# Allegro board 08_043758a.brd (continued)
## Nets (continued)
DDR3_A10: R21.1(N1) U2.L7(A10/AP) U4.J1(PS_DDR_A10_502)
DDR3_A11: R27.1(N1) U2.R7(A11) U4.L2(PS_DDR_A11_502)
DDR3_A12: R28.1(N1) U2.N7(A12/BC#) U4.M2(PS_DDR_A12_502)
DDR3_A13: R34.1(N1) U2.T3(A13) U4.K2(PS_DDR_A13_502)
DDR3_A14: R29.1(N1) U2.T7(A14) U4.K1(PS_DDR_A14_502)
DDR3_BA0: R35.1(N1) U2.M2(BA0) U4.M6(PS_DDR_BA0_502)
DDR3_BA1: R30.1(N1) U2.N8(BA1) U4.R1(PS_DDR_BA1_502)
DDR3_BA2: R36.1(N1) U2.M3(BA2) U4.N6(PS_DDR_BA2_502)
DDR3_CAS#: R32.1(N1) U2.K3(CAS#) U4.R5(PS_DDR_CAS_B_502)
DDR3_CK_N: R142.2(N2) U2.K7(CK#) U4.N2(PS_DDR_CKN_502)
DDR3_CK_P: R142.1(N1) U2.J7(CK) U4.N3(PS_DDR_CKP_502)
DDR3_CKE: R38.1(N1) U2.K9(CKE) U4.L3(PS_DDR_CKE_502)
DDR3_CS#: R39.1(N1) U2.L2(CS#) U4.R2(PS_DDR_CS_B_502)
DDR3_DM0: U2.E7(LDM) U4.B1(PS_DDR_DM0_502)
DDR3_DM1: U2.D3(UDM) U4.D3(PS_DDR_DM1_502)
DDR3_DQ0: U2.E3(DQ0) U4.D4(PS_DDR_DQ0_502)
DDR3_DQ1: U2.F7(DQ1) U4.A2(PS_DDR_DQ1_502)
DDR3_DQ2: U2.F2(DQ2) U4.C4(PS_DDR_DQ2_502)
DDR3_DQ3: U2.F8(DQ3) U4.C1(PS_DDR_DQ3_502)
DDR3_DQ4: U2.H3(DQ4) U4.B4(PS_DDR_DQ4_502)
DDR3_DQ5: U2.H8(DQ5) U4.A4(PS_DDR_DQ5_502)
DDR3_DQ6: U2.G2(DQ6) U4.C3(PS_DDR_DQ6_502)
DDR3_DQ7: U2.H7(DQ7) U4.A3(PS_DDR_DQ7_502)
DDR3_DQ8: U2.D7(DQ8) U4.E1(PS_DDR_DQ8_502)
DDR3_DQ9: U2.C3(DQ9) U4.D1(PS_DDR_DQ9_502)
DDR3_DQ10: U2.C8(DQ10) U4.E2(PS_DDR_DQ10_502)
DDR3_DQ11: U2.C2(DQ11) U4.E3(PS_DDR_DQ11_502)
DDR3_DQ12: U2.A7(DQ12) U4.F3(PS_DDR_DQ12_502)
DDR3_DQ13: U2.A2(DQ13) U4.G1(PS_DDR_DQ13_502)
DDR3_DQ14: U2.B8(DQ14) U4.H1(PS_DDR_DQ14_502)
DDR3_DQ15: U2.A3(DQ15) U4.H2(PS_DDR_DQ15_502)
DDR3_DQS0_N: U2.G3(LDQS#) U4.B2(PS_DDR_DQS_N0_502)
DDR3_DQS0_P: U2.F3(LDQS) U4.C2(PS_DDR_DQS_P0_502)
DDR3_DQS1_N: U2.B7(UDQS#) U4.F2(PS_DDR_DQS_N1_502)
DDR3_DQS1_P: U2.C7(UDQS) U4.G2(PS_DDR_DQS_P1_502)
DDR3_ODT: R33.1(N1) U2.K1(ODT) U4.K3(PS_DDR_ODT_502)
DDR3_RAS#: R37.1(N1) U2.J3(RAS#) U4.R6(PS_DDR_RAS_B_502)
DDR3_RST#: R42.1(N1) U2.T2(RESET#) U4.L4(PS_DDR_DRST_B_502)
DDR3_WE#: R31.1(N1) U2.L3(WE#) U4.R3(PS_DDR_WE_B_502)
FB0: R2.2(N2) R4.1(N1) U3.4(FB)
FB_1P8V: R64.1(N1) R65.2(N2) U6.32(FB1)
FB_1P35V: R62.2(N2) R63.1(N1) U6.9(FB2)
IO_02_34_AD9361_CLKOUT: U4.P8(IO_L23P_T3_34) U5.J6(CLK_OUT)
IO_02_34_AD9361_RST: U4.P9(IO_L23N_T3_34) U5.K5(RESETB)
IO_L01_34_FB_CLK: U4.P10(IO_L24P_T3_34) U5.F10(FB_CLK_P)
IO_L01_34_RX_D0: U4.H14(IO_L3N_T0_DQS_34) U5.K11(P1_D0/RX_D0_N)
IO_L01_34_RX_D1: U4.J13(IO_L5P_T0_34) U5.J12(P1_D1/RX_D0_P)
IO_L02_34_RX_D2: U4.G14(IO_L3P_T0_DQS_PUDC_B_34) U5.K10(P1_D2/RX_D1_N)
IO_L02_34_RX_D3: U4.H13(IO_L2N_T0_34) U5.J11(P1_D3/RX_D1_P)
IO_L03_34_RX_D4: U4.G12(IO_L2P_T0_34) U5.K9(P1_D4/RX_D2_N)
IO_L03_34_RX_D5: U4.H12(IO_L1N_T0_34) U5.J10(P1_D5/RX_D2_P)
IO_L04_34_RX_D6: U4.G11(IO_L1P_T0_34) U5.K8(P1_D6/RX_D3_N)
IO_L04_34_RX_D7: U4.J14(IO_L5N_T0_34) U5.J9(P1_D7/RX_D3_P)
IO_L05_34_RX_D8: U4.J15(IO_L4P_T0_34) U5.K7(P1_D8/RX_D4_N)
IO_L05_34_RX_D9: U4.K15(IO_L4N_T0_34) U5.J8(P1_D9/RX_D4_P)
IO_L06_34_RX_D10: U4.H11(IO_L6P_T0_34) U5.J7(P1_D10/RX_D5_N)
IO_L06_34_RX_D11: U4.J11(IO_L6N_T0_VREF_34) U5.H8(P1_D11/RX_D5_P)
IO_L07_34_RX_FRAME: U4.N13(IO_L7P_T1_34) U5.G8(RX_FRAME_P)
IO_L08_34_CTRL_OUT0: U4.L15(IO_L8P_T1_34) U5.D4(CTRL_OUT0)
IO_L08_34_CTRL_OUT1: U4.M15(IO_L8N_T1_34) U5.E4(CTRL_OUT1)
IO_L09_34_TX_FRAME: U4.L14(IO_L9P_T1_DQS_34) U5.G9(TX_FRAME_P)
IO_L10_34_EN_AGC: U4.L13(IO_L10N_T1_34) U5.G5(EN_AGC)
IO_L11_34_ENABLE: U4.K12(IO_L11N_T1_SRCC_34) U5.G6(ENABLE)
IO_L11_34_TXNRX: U4.K11(IO_L11P_T1_SRCC_34) U5.H4(TXNRX)
IO_L12_MRCC_34_DATA_CLK: U4.L12(IO_L12P_T1_MRCC_34) U5.G11(DATA_CLK_P)
IO_L13_34_CTRL_OUT2: U4.N11(IO_L13P_T2_MRCC_34) U5.E5(CTRL_OUT2)
IO_L13_34_CTRL_OUT3: U4.N12(IO_L13N_T2_MRCC_34) U5.E6(CTRL_OUT3)
IO_L15_34_TX_D0: U4.P15(IO_L15P_T2_DQS_34) U5.E12(P0_D0/TX_D0_N)
IO_L15_34_TX_D1: U4.R13(IO_L17N_T2_34) U5.D11(P0_D1/RX_D0_P)
IO_L16_34_TX_D2: U4.R15(IO_L15N_T2_DQS_34) U5.E11(P0_D2/TX_D1_N)
IO_L16_34_TX_D3: U4.P11(IO_L16P_T2_34) U5.D10(P0_D3/TX_D1_P)
IO_L17_34_TX_D4: U4.R11(IO_L16N_T2_34) U5.E10(P0_D4/TX_D2_N)
IO_L17_34_TX_D5: U4.R12(IO_L17P_T2_34) U5.D9(P0_D5/TX_D2_P)
IO_L18_34_TX_D6: U4.P14(IO_L18N_T2_34) U5.E9(P0_D6/TX_D3_N)
IO_L18_34_TX_D7: U4.P13(IO_L18P_T2_34) U5.D8(P0_D7/TX_D3_P)
IO_L19_34_TX_D8: U4.N9(IO_L19N_T3_VREF_34) U5.E8(P0_D8/TX_D4_N)
IO_L19_34_TX_D9: U4.M9(IO_L19P_T3_34) U5.D7(P0_D9/TX_D4_P)
IO_L20_34_TX_D10: U4.R8(IO_L20N_T3_34) U5.F8(P0_D10/TX_D5_N)
IO_L20_34_TX_D11: U4.R7(IO_L20P_T3_34) U5.E7(P0_D11/TX_D5_P)
IO_L21_34_CTRL_OUT4: U4.M10(IO_L21P_T3_DQS_34) U5.F6(CTRL_OUT4)
IO_L21_34_CTRL_OUT5: U4.M11(IO_L21N_T3_DQS_34) U5.F5(CTRL_OUT5)
IO_L22_34_CTRL_OUT6: U4.N7(IO_L22P_T3_34) U5.F4(CTRL_OUT6)
IO_L22_34_CTRL_OUT7: U4.N8(IO_L22N_T3_34) U5.G4(CTRL_OUT7)
IO_L23_35_SPI_CLK: U4.E11(IO_L2P_T0_AD8P_35) U5.J5(SPI_CLK)
IO_L23_35_SPI_ENB: U4.E12(IO_L2N_T0_AD8N_35) U5.K6(SPI_ENB)
IO_L24_35_SPI_DI: U4.E13(IO_L1N_T0_AD0N_35) U5.J4(SPI_DI)
IO_L24_35_SPI_DO: U4.F12(IO_L1P_T0_AD0P_35) U5.L6(SPI_DO)
JTAG_TCK: P1.4(N2) U4.G9(TCK_0)
JTAG_TDI: P1.8(N4) U4.L7(TDI_0)
JTAG_TDO: P1.6(N3) U4.L8(TDO_0)
JTAG_TMS: P1.2(N1) U4.L9(TMS_0)
PG_1P0V: R6.2(N2) U3.16(PGOOD) U6.28(EN1)
PG_1P8V: R59.1(N1) U6.13(EN2) U6.29(PGOOD1)
PS-SRST#: R11.2(N2) R74.2(N2) U4.B11(PS_SRST_B_501)
PS_MIO01_500_QSPI0_SS_B: R14.2(N2) U4.A5(PS_MIO1_500) U13.C2(S#)
PS_MIO02_500_QSPI0_IO0: R120.1(N1) U4.A8(PS_MIO2_500) U13.D3(DQ0)
PS_MIO03_500_QSPI0_IO1: R119.1(N1) U4.A7(PS_MIO3_500) U13.D2(DQ1)
PS_MIO04_500_QSPI0_IO2: R121.1(N1) U4.C8(PS_MIO4_500) U13.C4(W#/VPP/DQ2)
PS_MIO05_500_QSPI0_IO3: P1.5(N3) R122.1(N1) U4.A9(PS_MIO5_500) U13.D4(HOLD#/DQ3)
PS_MIO06_500_QSPI0_SCLK: R116.1(N1) U4.A10(PS_MIO6_500) U13.B2(C)
PS_MIO07_500_USB_RESET_B: R76.2(N2) U4.A12(PS_MIO52_501) U15.27(RESETB)
PS_MIO28_501_USB0_D4: U4.A15(PS_MIO28_501) U15.7(DATA4)
PS_MIO29_501_USB0_DIR: U4.D11(PS_MIO29_501) U15.31(DIR)
PS_MIO30_501_USB0_STP: U4.B15(PS_MIO30_501) U15.29(STP)
PS_MIO31_501_USB0_NXT: U4.C12(PS_MIO31_501) U15.2(NXT)
PS_MIO32_501_USB0_D0: U4.E15(PS_MIO32_501) U15.3(DATA0)
PS_MIO33_501_USB0_D1: U4.C11(PS_MIO33_501) U15.4(DATA1)
PS_MIO34_501_USB0_D2: U4.D15(PS_MIO34_501) U15.5(DATA2)
PS_MIO35_501_USB0_D3: U4.A14(PS_MIO35_501) U15.6(DATA3)
PS_MIO36_501_USB0_CLK: U4.B14(PS_MIO36_501) U15.1(CLKOUT)
PS_MIO37_501_USB0_D5: U4.C14(PS_MIO37_501) U15.9(DATA5)
PS_MIO38_501_USB0_D6: U4.A13(PS_MIO38_501) U15.10(DATA6)
PS_MIO39_501_USB0_D7: U4.D14(PS_MIO39_501) U15.13(DATA7)
PWR_GD: R5.2(N2) U1.5(PG) U7.5(PG)
PWR_GD_1.35V: C47.1(N1) R13.2(N2) R15.1(N1) U4.C9(PS_POR_B_500) U6.12(PGOOD2)
REF_CLK_SG: R10.1(N1) R50.1(N1)
RX1A_N: C133.2(N2) U5.M2(RX1A_N)
RX1A_P: C134.2(N2) U5.M1(RX1A_P)
SCL: R79.2(N2) R86.2(N2) U4.M14(IO_L9N_T1_DQS_34) U11.2(SCLA)
SDA: R78.2(N2) R85.2(N2) U4.N14(IO_L7N_T1_34) U11.3(SDAA)
SYNC: L4.1(N1) U3.9(SW_1) U3.10(SW_2) U3.11(SW_3)
TX1A_N: C131.1(N1) L8.2(N2) U5.M8(TX1A_N)
TX1A_P: C132.1(N1) L9.2(N2) U5.M7(TX1A_P)
TX_VCO_1P1V_SUPPLY: C128.1(N1) R52.1(N1) U5.A11(VDDA1P1_TX_VCO) U5.B11(TX_VCO_LDO_OUT)
UART_RX: P1.1(N1) U4.C6(PS_MIO13_500)
UART_TX: P1.3(N2) U4.B7(PS_MIO12_500)
UNNAMED_2_ADP1754_I93_SS: C2.1(N1) U1.7(SS)
UNNAMED_2_ADP1754_I233_SS: C12.1(N1) U7.7(SS)
UNNAMED_2_ADP2164_I29_EN: C13.1(N1) R1.1(N1) U3.1(SYNC) U3.3(TRK) U3.14(VIN) U3.15(EN)
UNNAMED_2_ADP2164_I29_PVIN1: C11.1(N1) L1.2(N2) R1.2(N2) R6.1(N1) U3.12(PVIN_1) U3.13(PVIN_2)
UNNAMED_2_ADP2164_I29_RT: R3.2(N2) U3.2(RT)
UNNAMED_2_RES_I251_N2: R4.2(N2) R7.1(N1)
UNNAMED_3_ICN25Q256AV2_I26_RESE: R11.1(N1) U13.A4(RESET/NC)
UNNAMED_3_ICXC7Z010_I16_PSCLK50: R10.2(N2) R12.2(N2) U4.C7(PS_CLK_500)
UNNAMED_3_ICXC7Z010_I16_PSMIO75: R83.2(N2) U4.D9(PS_MIO7_500)
UNNAMED_3_ICXC7Z010_I16_PSMIO85: R84.1(N1) U4.B6(PS_MIO8_500)
UNNAMED_3_RES_I2_N1: R8.2(N2) R9.1(N1) Y2.1(STANDBY)
UNNAMED_3_RES_I48_N1: R12.1(N1) Y2.3(OUTPUT)
UNNAMED_4_ICMT41K256M16_I98_ZQ: R165.1(N1) U2.L8(ZQ)
UNNAMED_4_ICTPS51206_I44_S3: R222.2(N2) U14.7(S3)
UNNAMED_4_ICTPS51206_I44_S5: R221.2(N2) U14.9(S5)
UNNAMED_4_ICTPS51206_I44_VLDOIN: R44.2(N2) U14.2(VLDOIN)
UNNAMED_4_ICTPS51206_I44_VTTSNS: C80.1(N1) R43.2(N2) U14.5(VTTSNS)
UNNAMED_4_ICXC7Z010_I26_PSDDR_1: R40.1(N1) U4.H3(PS_DDR_VRP_502)
UNNAMED_4_ICXC7Z010_I26_PSDDRVR: R41.1(N1) U4.J3(PS_DDR_VRN_502)
UNNAMED_5_CAP_I17_N1: C93.1(N1) C98.1(N1) E5.2(N2) U4.F7(VCCADC_0)
UNNAMED_5_CAP_I17_N2: C93.2(N2) C98.2(N2) E6.2(N2) U4.F6(CFGBVS_0) U4.F8(GNDADC_0) U4.G8(VREFN_0) U4.H7(VREFP_0) U4.J7(DXP_0)
UNNAMED_5_DIOLED_I60_N: DS1.C(N) R48.1(N1)
UNNAMED_5_DIOLED_I62_N: DS2.C(N) R87.1(N1)
UNNAMED_5_ICXC7Z010_I13_DONE0: Q1.1(G) U4.M7(DONE_0)
UNNAMED_5_ICXC7Z010_I13_INITB0: R47.1(N1) U4.D5(INIT_B_0)
UNNAMED_5_ICXC7Z010_I13_PROGRAM: R46.1(N1) U4.K6(PROGRAM_B_0)
UNNAMED_5_ICXC7Z010_I13_VCCBATT: R45.2(N2) U4.E6(VCCBATT_0)
UNNAMED_5_RES_I61_N2: Q1.3(D) R48.2(N2)
UNNAMED_5_RES_I63_N2: Q4.3(D) R87.2(N2)
UNNAMED_7_AD9363_I13_RBIAS: R49.2(N2) U5.L4(RBIAS)
UNNAMED_7_AD9363_I13_XTALN: C123.2(N2) C124.1(N1) U5.M12(XTALN)
UNNAMED_7_CAP_I22_N2: C126.2(N2) R51.1(N1)
UNNAMED_7_CAP_I30_N1: C127.1(N1) R52.2(N2)
UNNAMED_7_CAP_I39_N2: C132.2(N2) T5.4(SEC)
UNNAMED_7_CAP_I40_N2: C131.2(N2) T5.6(SEC_DOT)
UNNAMED_7_CAP_I51_N1: C134.1(N1) T1.4(SEC)
UNNAMED_7_CAP_I52_N1: C133.1(N1) T1.6(SEC_DOT)
UNNAMED_7_CAP_I53_N1: C123.1(N1) R50.2(N2) Y3.3(OUT)
UNNAMED_7_CNBNC5P_I55_CNTR: RX1A.1(CNTR) T1.3(PRI_DOT)
UNNAMED_7_CNBNC5P_I56_CNTR: T5.3(PRI_DOT) TX1A.1(CNTR)
UNNAMED_9_ADM1177_I23_GATE: Q3.1(G) U10.10(GATE)
UNNAMED_9_ADM1177_I23_ON: R71.2(N2) R72.1(N1) U10.3(ON)
UNNAMED_9_ADM1177_I23_SENSE: Q3.3(D) R73.2(N2) U10.2(SENSE)
UNNAMED_9_ADM1177_I23_SS: C155.1(N1) U10.9(SS)
UNNAMED_9_ADM1177_I23_TIMER: C156.1(N1) U10.5(TIMER)
UNNAMED_9_ADP2114_I196_FREQ: R53.2(N2) U6.3(FREQ)
UNNAMED_9_ADP2114_I196_OPCFG: R54.1(N1) U6.6(OPCFG)
UNNAMED_9_ADP2114_I196_SS1: C7.2(N2) U6.30(SS1)
UNNAMED_9_ADP2114_I196_SS2: C139.2(N2) U6.11(SS2)
UNNAMED_9_ADP2114_I196_SW1: L3.1(N1) U6.23(SW2) U6.24(SW1)
UNNAMED_9_ADP2114_I196_SW3: L2.1(N1) U6.17(SW4) U6.18(SW3)
UNNAMED_9_CAP_I163_N1: C146.1(N1) L3.2(N2) L5.1(N1)
UNNAMED_9_CAP_I214_N2: C147.2(N2) R60.2(N2)
UNNAMED_9_CAP_I224_N2: C144.2(N2) R61.2(N2)
UNNAMED_9_CAP_I306_N1: C149.1(N1) C150.1(N1) E3.1(N1) L5.2(N2) R64.2(N2)
UNNAMED_9_CN5P3SHLD_I255_N6: P2.SH1(N6) P2.SH2(N7) P2.SH3(N8) R55.1(N1)
UNNAMED_9_CN5P3SHLD_I256_N6: P3.SH1(N6) P3.SH2(N7) P3.SH3(N8) R58.1(N1)
UNNAMED_9_FERRITE_I303_N1: E7.1(N1) Q3.2(S)
UNNAMED_9_ICNCP339_I277_EN: R68.2(N2) R69.1(N1) U8.C2(EN)
UNNAMED_9_ICNCP339_I278_EN: Q2.3(D) R70.2(N2) U9.C2(EN)
UNNAMED_9_RES_I270_N1: Q2.1(G) R66.2(N2) R67.1(N1)
UNNAMED_11_ICUSB3320C_I29_RBIAS: R77.1(N1) U15.24(RBIAS)
UNNAMED_11_ICUSB3320C_I29_REFCL: R82.1(N1) U15.26(REFCLK)
UNNAMED_11_ICUSB3320C_I29_VBUS: R75.2(N2) U15.22(VBUS)
UNNAMED_11_ICXC7Z010_I11_PSMI_1: R85.1(N1) U4.D13(PS_MIO49_501)
UNNAMED_11_ICXC7Z010_I11_PSMIO4: R86.1(N1) U4.B12(PS_MIO48_501)
UNNAMED_11_RES_I67_N2: R82.2(N2) Y1.3(OUTPUT)
USB_OTG_N: D2.C(N) P2.2(N2) U15.19(DM)
USB_OTG_P: D1.C(N) P2.3(N3) U15.18(DP)
USR_LED: Q4.1(G) U4.K13(IO_L10P_T1_34)
VTT_0P75: C79.1(N1) C101.1(N1) R16.2(N2) R17.2(N2) R18.2(N2) R19.2(N2) R20.2(N2) R21.2(N2) R22.2(N2) R23.2(N2) R24.2(N2) R25.2(N2) R26.2(N2) R27.2(N2) R28.2(N2) R29.2(N2) R30.2(N2) R31.2(N2) R32.2(N2) R33.2(N2) R34.2(N2) R35.2(N2) R36.2(N2) R37.2(N2) R38.2(N2) R39.2(N2) R43.1(N1) U14.3(VTT)
VTTVREF: C63.2(N2) C81.1(N1) C84.1(N1) C99.2(N2) C102.1(N1) U2.H1(VREFDQ) U2.M8(VREFCA) U4.F4(PS_DDR_VREF0_502) U14.6(VTTREF)

Pads without a net: P2 4; P3 2 3 4; U1 8; U2 J1 J9 L1 L9 M7; U4 B5 B9 B10 C13 D6 D8 D10 G7 H8 M12 R10; U5 A3 B3 B4 B5 B6 B7 C3 G7 H11 L5 M3 M11; U6 5; U7 8; U10 8; U11 5; U13 A2 A3 A5 B1 B5 C1 C3 C5 D1 D5 E1 E2 E3 E4 E5; U15 12 15 16 17 25; Y1 1; Y3 1

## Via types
v1: diameter 0.508, hole 0.254, TOP to BOTTOM, 797 vias
v2: diameter 0.406, hole 0.203, TOP to BOTTOM, 583 vias

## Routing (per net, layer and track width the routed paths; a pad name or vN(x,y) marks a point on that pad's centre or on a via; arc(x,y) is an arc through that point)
1.0V: length 20.7
  TOP w0.762: E1.1 74.65,15.95 ; E1.1 73.82,16.84 ; E1.1 73.82,15.06 ; 85.13,14.81 L4.2 ; L4.2 86.12,12.71 ; L4.2 86.12,16.9 ; 80.07,16.77 C17.1 ; C17.1 81.13,15.87 ; C17.1 82.18,16.77 ; 82.48,16.77 C21.1 ; C21.1 84.59,16.77 ; C21.1 83.54,15.87 ; C20.1 79.77,16.77 ; C20.1 77.66,16.77 ; C20.1 78.71,15.87 ; 76.3,15.87 C19.1 ; C19.1 77.35,16.77 ; C19.1 75.25,16.77
  BOTTOM w0.305: R7.2 v1(84.94,17.1)
1.35V: length 16.2
  TOP w0.762: C145.1 82.56,55.76 ; C145.1 81.51,56.67 ; C145.1 80.45,55.76 ; L2.2 88.11,56.53 ; L2.2 90.21,55.53 ; L2.2 86.01,55.53 ; C148.1 85.1,55.76 ; C148.1 82.99,55.76 ; C148.1 84.05,56.67 ; 79.28,56.72 E2.1 80.11,55.83
  BOTTOM w0.305: R62.1 92.3,55.99 92.3,56.59 92.05,56.84 v1(90.27,56.84)
1V8: length 123.4
  TOP w0.203: U1.4 20.63,9.26 20.47,9.09 20.1,9.09 19.98,9.21 ; 41.57,9.21 41.69,9.09 42.06,9.09 42.22,9.26 U7.4
  TOP w0.305: v1(75.79,29.28) 75.8,29.27 U15.30 ; U4.G4 v2(55.53,36.95) ; U11.1 57.61,14.26 C166.2 57.06,15.25 v1(57.24,15.43) ; U15.32 74.8,28.62 v1(74.27,29.16) ; U4.A6 v2(60.43,34.95) ; v1(82.27,30.68) C163.2 80.93,31.25 Y1.4 ; U4.K8 v2(52.33,33.75) ; U4.H4 v2(54.73,36.95) ; C10.1 41.57,8.91 ; C10.1 41.57,8 ; C10.1 41.16,8.46 ; Y3.4 25.06,17.67 C122.1 25.06,14.58 C121.1 25.37,14.21 v1(25.37,13.28) ; 18.25,9.98 U1.1 ; U1.1 18.68,9.21 ; U1.1 U1.2 U1.3 19.98,9.21 ; U4.N10 v2(49.93,31.35) ; 16.98,10.91 U1.16 ; U1.16 17.76,10.48 ; U1.16 U1.15 ; U4.E14 v2(57.13,28.15) ; v1(55.47,12.01) R78.1 ; R47.2 v1(65.12,39.32) ; U4.L6 v2(52.33,34.55) ; R84.2 v1(67.66,38.54) ; U15.8 v1(74.1,23.44) ; U15.14 77.3,22.44 v1(77.44,22.3) ; U4.R14 v2(48.33,28.15) ; C25.1 31.94,12.27 ; C25.1 31.53,12.72 ; C25.1 31.53,11.81 ; U4.C10 v2(58.73,31.35) ; U4.P7 v2(49.13,34.55) ; 38.57,10.91 U7.16 ; U7.16 U7.15 ; U7.16 39.35,10.48 ; 40.27,9.21 U7.1 ; U7.1 39.84,9.98 ; U7.1 U7.2 U7.3 41.57,9.21 ; U4.H9 v2(54.73,32.95) ; U4.D7 v2(57.93,34.55) ; 19.57,8.46 C1.1 ; C1.1 19.98,8.91 ; C1.1 19.98,8 ; U4.M13 v2(50.73,28.95) ; U13.B4 v2(73.61,45.31) ; U4.F11 v2(56.33,30.55) ; U4.J4 v2(53.13,36.95) ; U4.J6 v2(53.13,35.35) ; R74.1 65.25,29.78 v1(65.25,29.54) ; R8.1 v1(72.6,36.9) ; U4.J12 v2(53.13,29.75) ; v1(55.47,13.66) R79.1 ; v1(76.81,29.28) 76.8,29.28 U15.28 ; U15.11 v1(75.8,22.31) ; U4.B13 v2(59.53,28.95) ; U4.H15 v2(54.33,27.15) ; v1(71.47,35.25) 71.54,35.19 C46.1 70.15,34.62 Y2.4 ; U4.J8 v2(53.13,33.75) ; U4.K9 v2(52.33,32.95)
  TOP w0.508: 40.18,50.89 R44.1 ; R44.1 40.74,50.33 ; R44.1 41.3,50.89
  TOP w0.635: C22.1 32.42,11.06 ; C22.1 32.42,9.66 ; C22.1 33.06,10.36 ; 81.06,51.38 C152.1 81.7,50.68 ; 81.06,49.6 C153.1 81.7,50.3 ; 32.36,12.2 E4.1 ; E4.1 33.25,11.38 ; E4.1 34.14,12.2
  TOP w0.762: 39.94,45.07 C82.1 ; C82.1 40.74,45.92 ; C82.1 39.94,46.77 ; C83.1 40.74,48.71 ; C83.1 39.94,47.86 ; C83.1 39.94,49.57 ; E3.2 80.11,49.54 ; E3.2 79.22,50.37 ; E3.2 78.33,49.54
  BOTTOM w0.305: v2(58.73,31.35) 59.23,31.35 C69.1 ; v2(58.73,31.35) 58.45,31.35 C162.1 ; v2(58.73,31.35) 58.73,30.45 R76.1 ; v2(57.13,28.15) 56.91,28.36 C161.1 ; v2(54.33,27.15) 54.35,27.16 C119.1 ; C113.1 v2(59.83,25.64) C107.1 ; C168.1 v1(76.81,29.28) C140.1 ; v2(57.14,25.64) 56.96,25.46 C117.1 ; C110.1 50.82,29.04 v2(50.73,28.95) 50.63,28.85 C118.1 ; v1(75.79,29.28) C154.1 ; R83.1 64.14,32.75 v1(64.23,32.84) ; R45.1 60.93,33.65 60.61,33.97 C53.1 60.43,34.63 v2(60.43,34.95) 60.43,35.27 C52.1 ; C120.1 49.13,33.85 ; R13.1 73.16,32.79 v1(73.16,33.6) ; v2(73.61,45.31) 73.23,45.69 C48.1 ; C90.1 v2(46.62,32.56) C78.1 ; C108.1 v2(46.62,30.94)
  BOTTOM w0.406: C109.1 v2(54.34,25.64) C105.1 ; v2(59.53,28.95) 59.52,28.94 C111.1 ; v2(43.15,30.17) 43.15,30.95 C77.1 43.57,31.42 43.17,31.82 v2(43.17,32.59) ; C115.1 v2(57.14,25.64) ; C112.1 48.33,28.65 v2(48.33,28.15) 48.33,27.64 C114.1 ; 49.13,33.85 49.13,33.85 v2(49.13,34.55) 48.61,34.55 48.29,34.24 C51.1 ; v2(62.83,28.45) 62.83,27.8 C103.1 62.03,27.8 v2(62.03,28.45) 62.04,28.45 C160.1 v2(62.04,29.75) C159.1 62.04,30.94 v2(62.03,30.95) 62.04,30.95 C50.1 ; C106.1 v2(51.93,25.64) C67.1 ; C116.1 49.32,31.35 v2(49.93,31.35) 50.63,32.05 R46.2
  BOTTOM w0.508: v1(44.04,34.24) 44.04,35.73 C76.1 v1(44.02,37.16) ; v1(72.62,50.87) R14.1 ; v2(47.34,24.73) 48.31,24.73 C65.1 48.68,24.71 v2(49.63,24.71) ; v2(44.42,24.71) 45.38,24.71 C104.1 45.74,24.73 v2(46.71,24.73) ; v1(70.58,42.75) R122.2
  BOTTOM w0.635: v1(68.58,38.92) C174.1 68.04,37.92 67.54,37.41 L12.1 ; v1(68.3,44.9) 67.66,44.9 67.03,44.27 E5.1 67.35,43.89 v1(68.3,43.89)
  BOTTOM w0.762: C49.1 65.25,32.57 ; C49.1 64.2,31.32 ; C49.1 65.25,30.06 ; 65.25,29.14 C158.1 64.2,27.89
  vias: v1(18.64,8.33) v1(18.64,7.69) v1(18.64,7.06) v1(19.28,8.33) v1(19.28,7.69) v1(19.28,7.06) v1(19.91,7.69) v1(19.91,7.06) v1(33.5,11) v1(33.5,10.36) v1(33.5,9.73) v1(34.14,11) v1(34.14,10.36) v1(34.14,9.73) v1(39.6,47.32) v1(40.23,8.33) v1(40.23,7.69) v1(40.23,7.06) v1(40.49,47.32) v1(40.87,8.33) v1(40.87,7.69) v1(40.87,7.06) v1(41.37,49.35) v1(41.37,48.33) v1(41.37,47.32) v1(41.37,46.3) v1(41.37,45.29) v1(41.5,7.69) v1(41.5,7.06) v1(64.49,29.54) v1(64.88,32.84) v1(65.52,32.84) v1(65.89,29.54) v1(78.46,51.38) v1(78.46,50.62) v1(79.22,51.38) v1(79.22,50.62) v1(79.98,51.38) v1(79.98,50.62) v1(80.74,51.38) v1(80.74,50.62) v1(80.74,49.86) v1(80.74,49.1)
1V35: length 35.4
  TOP w0.203: v1(39.34,51.64) 39.34,52.11 39.22,52.23 U14.1
  TOP w0.305: U2.D9 v2(58.42,48.67) ; U2.C9 v2(60.02,48.67) ; U2.A8 v2(61.62,49.47) ; U4.E4 v2(57.13,36.95) ; U2.H9 v2(55.22,48.67) ; U2.N1 v2(51.22,55.87) ; U2.R1 v2(49.62,55.87) ; U2.C1 v2(60.02,55.87) ; U2.K8 v2(53.62,49.47) ; U2.N9 51.62,49.07 v2(52.02,49.47) ; U4.F1 55.53,39.35 v2(55.53,39.35) ; U2.D2 v2(59.22,55.07) ; U4.R4 v2(48.23,36.55) ; U2.A1 v2(61.62,55.87) ; U2.H2 v2(56.02,55.07) ; U2.G7 v2(56.82,51.07) ; U2.R9 v2(50.42,49.47) ; C60.1 63.22,38.07 v2(63.14,38.16) ; U4.M3 v2(50.73,37.75) ; U4.J2 v2(53.13,38.55) ; U4.B3 v2(59.53,37.75) ; U2.F1 v2(57.62,55.87) ; U2.B2 v2(60.82,55.07) ; U2.E9 v2(57.62,48.67) ; U2.K2 v2(53.62,55.07)
  TOP w0.406: C58.1 52.23,42.15 v2(51.73,42.15) ; C56.1 v1(45.82,35.27) ; v2(53.53,42.15) 54.03,42.15 C57.1
  TOP w0.635: C151.1 77.63,54.11 ; C151.1 77,53.41 ; C151.1 77.63,52.71
  TOP w0.762: 77.38,54.94 E2.2 ; E2.2 77.38,56.72 ; E2.2 76.55,55.83
  TOP w1.016: 65.63,53.5 C100.1 ; C100.1 64.37,54.56 ; C100.1 66.89,54.56
  BOTTOM w0.305: C91.1 55.3,48.75 v2(55.22,48.67) ; C89.1 54.22,54.47 v2(53.62,55.07) ; v2(50.42,49.47) 50.11,49.47 C86.1 ; v2(53.13,38.55) 53.63,38.55 R41.2 ; v2(56.82,51.07) 56.3,51.07 C92.1 ; v2(60.02,55.87) 59.84,56.05 C94.1 ; C88.1 61.62,56.47 v2(61.62,55.87) ; C61.1 47.52,36.34 ; C96.1 49.53,55.95 v2(49.62,55.87) ; C97.1 61.7,49.39 v2(61.62,49.47) ; v2(60.02,48.67) 60.63,48.67 C87.1 ; C95.1 57.71,55.96 v2(57.62,55.87)
  BOTTOM w0.406: v2(48.23,36.55) 47.73,36.55 47.52,36.34 ; v2(53.13,38.55) 53.12,38.56 C59.1 ; C55.1 55.53,39.76 55.53,39.35 v2(55.53,39.35)
  vias: v1(64.11,54.94) v1(64.11,53.92) v1(65.12,53.29) v1(66.14,53.29) v1(75.92,54.3) v1(75.92,53.67) v1(75.92,53.03) v1(75.92,52.4) v1(75.92,51.76) v1(76.55,54.3) v1(76.55,53.67) v1(76.55,53.03) v1(76.55,52.4) v1(76.55,51.76) v1(77.19,52.4) v2(56.11,43.57) v2(56.11,42.96)
GND: length 452
  TOP w0.152: U5.L7 26.75,32.08 28.34,32.08 U5.H7 ; U5.C7 32.34,32.08 v2(29.15,32.08)
  TOP w0.203: U14.8 36.29,53.03 ; U5.L8 26.06,31.16 26.06,31.39 U5.L7 ; U14.PAD 38.35,53.43 U14.4 39.74,53.43 v2(39.85,53.54) ; U8.C1 101.61,52.69 v1(101.19,52.27) ; D2.A v1(101.32,36.27)
  TOP w0.254: D1.A v1(102.46,33.73)
  TOP w0.305: U4.K10 v2(52.33,31.35) ; 40.27,56.17 C79.2 ; C79.2 41.97,56.17 ; C79.2 41.12,56.97 ; 19.44,39.3 T1.2 17.57,40.38 ; C33.2 31.21,17.09 v1(30.96,16.84) ; 50.42,48.23 v2(50.42,48.67) U2.P9 ; C13.2 90.07,25.21 ; C13.2 88.95,25.21 ; C13.2 89.51,25.77 ; C56.2 45.63,36.26 ; C56.2 45.07,36.82 ; C56.2 44.51,36.26 ; U5.M5 v2(25.14,32.88) U5.M6 ; U5.G10 v2(29.95,29.68) ; U5.A2 v2(34.74,36.08) ; 66.08,13.97 C167.2 ; C167.2 66.48,14.42 ; C167.2 66.08,14.87 v1(66.25,15.05) ; v1(67.28,36.14) 68.23,36.14 Y2.2 ; 30.49,12.27 C25.2 ; 26.96,19.12 Y3.2 ; Y3.2 27.81,20.07 ; Y3.2 26.96,21.02 ; Y3.2 26.11,20.07 ; U2.E1 v2(58.42,55.87) ; U5.E1 v2(30.74,36.88) U5.F1 ; v2(41.25,11.88) 41.57,11.56 U7.6 v1(44.04,11.56) 44.05,11.57 C12.2 ; C122.2 26.1,16.08 ; 25.95,26.5 v2(25.95,27.28) U5.L12 v2(25.95,28.08) U5.L11 v2(25.95,28.88) U5.L10 v2(25.95,29.68) U5.L9 v2(25.95,30.48) U5.L8 ; 67.92,5.38 P1.9 ; U4.E5 v2(57.13,36.15) ; C12.2 45.13,11.57 ; C12.2 44.68,11.16 ; U3.6 U3.5 ; U3.6 U3.7 ; U3.6 89.46,20.9 v2(89.78,20.57) 89.46,20.25 U3.7 ; U3.6 87.06,20.9 ; U3.5 87.81,21.98 ; U3.5 87.06,21.55 ; U3.5 88.72,21.55 v2(88.76,21.59) ; U2.E2 v2(58.42,55.07) ; U5.D12 v2(32.34,27.28) ; U5.C4 v2(33.14,34.48) ; C43.2 29.46,27.09 29.46,27.09 v2(29.46,27.14) 29.54,27.23 U5.G12 ; C43.2 29.87,25.88 ; C43.2 29.46,25.15 C45.2 ; U5.C1 v2(33.14,36.88) U5.B1 ; U6.22 92.2,49.74 ; U6.22 90.84,49.74 90.7,49.88 ; U6.22 91.5,50.15 ; T1.1 18.8,38.2 ; T1.1 16.93,39.28 ; T1.1 17.55,38.19 ; 51.77,43.05 C58.2 ; C58.2 52.89,43.05 ; C58.2 52.33,43.61 ; Y2.2 68.27,36.85 ; Y2.2 67.47,36.1 ; U2.G9 v2(56.82,48.67) ; U5.A1 v2(34.74,36.88) ; U4.B8 v2(58.73,33.75) ; U5.K12 v2(26.74,27.28) ; U5.K1 v2(26.74,36.88) U5.L1 ; U2.A9 v2(61.62,48.67) ; U4.G13 v2(55.53,28.95) ; U6.19 92.2,51.24 ; U6.19 91.5,50.84 ; U6.19 91.05,51.24 90.7,50.9 ; U2.D8 v2(58.42,50.27) ; 23.54,11.57 C2.2 22.46,11.57 v1(22.45,11.56) U1.6 19.98,11.56 v2(19.66,11.88) ; 81.57,25.65 C164.2 82.27,26.11 v1(82.52,26.36) ; U5.H6 v2(28.35,32.88) ; U4.N15 v2(50.33,27.25) ; U4.K7 v2(53.13,34.55) ; U5.A12 v2(34.74,27.28) ; U4.F10 v2(56.33,31.35) ; U5.C7 v2(33.14,31.28) U5.C8 v2(33.14,30.48) U5.C9 v2(33.14,29.68) U5.C10 v2(33.14,28.88) U5.C11 v2(33.14,28.08) U5.C12 v2(33.14,27.28) ; 23.89,24.33 C124.2 24.29,24.79 ; v1(72.24,35.25) 72.17,35.19 C46.2 ; U2.G1 v2(56.82,55.87) ; U5.A4 v2(34.74,34.48) ; 48.82,56.16 v2(48.82,55.87) U2.T1 ; 36.29,53.03 35.6,53.03 C84.2 34.9,53.22 v1(34.77,53.1) ; C62.1 37.78,51 ; C62.1 37.37,51.46 ; C62.1 37.37,50.54 ; 22.52,34.16 R49.1 ; R49.1 22.52,35.08 ; R49.1 22.11,34.62 ; U2.B3 v2(60.82,53.47) ; v1(96.61,37.28) R72.2 97.17,38.05 ; C16.2 40.23,17.18 ; C6.2 19.91,17.18 ; U2.G8 v2(56.82,50.27) ; 72.17,34.16 C46.2 ; C46.2 72.58,34.62 ; v1(58.89,11.64) U11.4 59.8,12.31 ; U2.P1 v2(50.42,55.87) 50.42,56.18 ; U4.D12 v2(57.93,29.75) ; 100.56,49.18 R61.1 101.12,49.74 ; 88.29,38.16 C155.2 v1(87.73,38.94) ; U2.B1 v2(60.82,55.87) ; U3.7 87.06,20.25 ; U3.7 U3.8 ; U5.F11 v2(30.74,28.08) ; U5.A5 v2(34.74,33.68) ; v2(88.76,19.56) 87.85,19.56 U3.8 ; C45.2 30.2,24.98 ; C45.2 29.64,24.42 ; U10.4 94.58,37.66 v1(94.84,37.92) ; U2.J2 v2(55.22,55.07) ; U4.E8 v2(57.13,33.75) ; R9.2 71.6,38.14 ; R9.2 71.14,37.73 ; R9.2 72.06,37.73 ; U4.J5 v2(53.93,35.35) ; v2(52.02,48.67) 52.42,49.07 U2.M9 ; C10.2 v1(42.77,8.46) ; U4.E9 v2(57.13,32.15) ; U5.H9 v2(29.15,30.48) ; U5.H7 v2(29.15,32.08) ; v1(97.25,48.21) 96.72,48.74 U6.1 ; v1(103.86,33.37) P2.5 ; 87.06,19.6 U3.8 ; U2.J8 v2(55.22,49.47) ; U5.F7 v2(30.74,31.28) ; U4.L11 v2(51.53,30.55) ; U2.M1 v2(52.02,55.87) 52.02,56.18 ; U5.L7 v2(25.94,32.08) ; U4.P2 v2(49.13,38.55) ; U5.H10 v2(29.15,29.68) ; U5.C2 v2(33.14,36.08) ; v1(101.32,38.43) 101.32,38.05 U9.C1 ; U4.P12 v2(49.13,29.75) ; U5.L3 v2(25.95,35.28) ; 48.82,48.51 v2(48.82,48.67) U2.T9 ; U2.F9 v2(56.82,49.47) ; U4.M8 v2(50.73,33.75) ; U5.H2 v2(28.35,36.08) U5.J2 ; U4.K4 v2(52.33,36.95) ; U5.M4 v2(25.14,34.48) ; U5.J1 v2(28.35,36.88) U5.H1 ; U5.G1 v2(29.14,36.88) ; U4.E7 v2(57.13,34.55) ; 96.81,20.82 C8.2 ; C8.2 96.81,21.74 ; C8.2 96.4,21.28 ; U4.G3 v2(55.53,37.75) ; C60.2 63.86,38.07 v2(63.94,38.16) ; U4.C5 v2(58.73,35.35) ; U4.H10 v2(54.73,31.35) ; 14.88,28.36 T5.1 ; 54.13,43.6 C57.2 53.57,43.05 ; U2.D1 v2(59.22,55.87) ; U5.L2 v2(26.74,36.08) U5.K2 ; 102.21,48.68 R69.2 ; R69.2 102.77,49.24 ; R69.2 v1(101.46,49.24) ; U4.N5 v2(49.93,36.15) ; U2.E8 v2(58.42,49.47) ; 82.27,32.29 C163.1 82.73,31.89 ; U5.F9 v2(30.74,29.68) ; v1(71.13,33.53) 70.93,33.73 67.16,33.73 67.03,33.86 v1(66.01,33.86) v1(64.87,33.86) 64.83,33.82 62.62,33.82 v1(62.33,34.11) ; 97.17,39.06 C156.2 v1(96.61,39.82) ; U4.A11 v2(60.53,30.95) ; U4.H6 v2(53.93,34.55) ; U4.L5 v2(51.53,36.15) ; U4.D2 v2(57.93,38.55) ; U5.B2 v2(33.94,36.08) ; U4.R9 v2(48.25,32.55) ; C5.2 18.64,17.18 ; 20.32,38.79 T1.5 ; 13.8,30.27 T5.2 ; 56.02,14.81 C166.1 ; U13.B3 v2(73.62,46.29) ; v2(60.33,39.35) U4.A1 ; U4.L1 v2(51.93,39.45) ; U5.A6 v2(34.74,32.88) ; U5.D1 v2(32.34,36.88) ; 66.65,5.38 P1.7 ; 99.02,50.29 R53.1 99.02,49.17 ; U4.J9 v2(53.13,32.95) ; U4.C15 v2(58.33,27.24) ; U2.B9 v2(60.02,49.47) ; U4.K14 v2(53.13,28.94) ; U5.B12 v2(33.94,27.28) ; U5.F3 v2(30.74,35.28) ; U5.H3 v2(28.35,35.28) ; C1.2 v1(21.18,8.46) ; C18.2 41.5,17.18 ; U5.H5 v2(28.35,33.68) ; U4.G5 v2(55.53,36.15)
  TOP w0.406: v2(53.53,42.85) 53.93,42.85 C57.2 ; v2(51.73,42.95) 52.23,42.95 C58.2 ; v1(77.95,32.54) Y1.2 v1(78.93,33.47) ; P3.5 v1(103.86,51.15)
  TOP w0.508: C121.2 27.53,14.55 ; C121.2 26.73,13.7 ; C121.2 26.73,15.4 ; v1(99.67,52.65) 99.27,52.65 C141.2 ; R53.1 v1(99.79,49.73) 99.81,49.74 R61.1 ; 56.43,20.58 C68.2 ; C143.1 v1(98.77,50.76)
  TOP w0.635: 30.39,15.95 C32.2 ; C32.2 31.02,16.65 ; C32.2 31.02,15.25 ; C151.2 79.03,54.11 ; C151.2 79.67,53.41 ; C151.2 79.03,52.71 ; 83.09,48.9 C153.2 ; C153.2 83.09,50.3 ; C153.2 83.73,49.6 ; v1(19.17,37.99) T1.1 v1(16.75,39.38) ; 31.02,9.66 C22.2 30.39,10.36 ; T1.5 19.89,39.04 ; C4.2 17.82,17.41 ; C4.2 17.12,18.04 ; C4.2 16.42,17.41 ; 14.9,13.6 C3.2 ; C3.2 14.26,14.3 ; C3.2 14.9,15 ; C14.2 39.41,17.41 ; C14.2 38.71,18.04 ; C14.2 38.01,17.41 ; C15.2 36.49,15 ; C15.2 35.85,14.3 ; C15.2 36.49,13.6 ; 83.09,50.68 C152.2 ; C152.2 83.09,52.08 ; C152.2 83.73,51.38 ; v1(13.58,29) T5.1 v1(16.46,29) ; v1(16.71,40.31) 16.88,40.48 17.4,40.48 T1.2 19.6,39.21 v1(19.71,38.81) ; T5.5 16.83,30.27 v1(16.48,29.92) 16.13,30.27 T5.2 14.82,30.22 13.58,30.22 v1(13.07,29.71) ; 95.92,19.38 C9.2 96.56,20.08
  TOP w0.762: 83.35,45.96 C150.2 84.25,44.9 ; C138.2 94.55,58.96 ; C138.2 95.35,58.11 ; C138.2 94.55,57.26 ; 60.64,19.7 C64.2 ; C64.2 61.9,18.64 ; C64.2 63.16,19.7 ; 82.48,18.68 C21.2 ; C21.2 84.59,18.68 ; C21.2 83.54,19.58 ; C149.2 83.35,48.5 ; C149.2 83.35,46.39 ; C149.2 84.25,47.44 ; 95.48,45.54 C135.2 94.68,44.69 ; C100.2 65.63,58.41 ; C100.2 66.89,57.35 ; C100.2 64.37,57.35 ; v1(37.95,51.76) U14.PAD 37.95,54.04 ; 38.14,54.77 C81.2 ; C81.2 39.04,55.83 ; C81.2 38.14,56.88 ; 94.68,42.15 C137.2 ; C137.2 94.68,43.85 ; C137.2 95.48,43 ; 38.24,47.86 C83.2 ; C83.2 38.24,49.57 ; C83.2 37.44,48.71 ; 81.76,35.14 C157.2 ; C157.2 80.71,36.4 ; C157.2 81.76,37.65 ; 37.44,45.92 C82.2 ; C82.2 38.24,46.77 ; C82.2 38.24,45.07 ; 81.51,52.96 C145.2 ; C145.2 82.56,53.86 ; C145.2 80.45,53.86 ; C54.2 61.27,43.06 ; C54.2 60.21,41.81 ; C54.2 60.21,44.32 ; C17.2 81.13,19.58 ; C17.2 80.07,18.68 ; C17.2 82.18,18.68 ; 75.25,18.68 C19.2 ; C19.2 76.3,19.58 ; C19.2 77.35,18.68 ; 77.66,18.68 C20.2 ; C20.2 79.77,18.68 ; C20.2 78.71,19.58 ; 94.55,56.42 C136.2 95.35,55.57 ; 58.65,18.7 C71.2 ; C71.2 59.9,19.76 ; C71.2 57.39,19.76 ; 84.05,52.96 C148.2 82.99,53.86
  TOP w1.016: C11.2 93.74,13.47 ; C11.2 91.63,13.47 ; C11.2 92.68,12.57
  L6_SIG w0.305: 66.65,5.38 P1.7 ; 67.92,5.38 P1.9
  BOTTOM w0.305: 48.67,30.45 C116.2 49.22,29.89 ; v2(33.14,34.48) 33.14,34.66 C42.2 ; 68.82,46.63 R120.2 ; 52.53,40.11 C59.2 51.97,39.55 ; C38.2 29.46,26.75 v2(29.46,27.14) C44.2 ; C38.2 29.64,26.02 ; C38.2 29.64,27.14 ; 58.75,56.48 C95.2 58.34,55.95 v2(58.42,55.87) ; 90.35,22.57 R3.1 ; R3.1 90.9,22.01 ; R3.1 91.46,22.57 ; C23.2 32.05,36.58 v2(32.34,36.88) ; v2(54.33,26.55) 54.35,26.53 C119.2 ; 101.03,11.17 Q4.2 ; Q4.2 101.98,10.41 ; Q4.2 101.98,11.94 ; Q4.2 102.93,11.17 ; 31.89,25.22 C30.2 ; C30.2 32.45,25.78 ; C30.2 31.89,26.34 ; C44.2 29.46,28.14 ; C44.2 29.87,27.68 ; v2(53.13,41.05) 53.63,41.05 R40.2 ; 58.38,39.45 C99.1 57.92,39.04 ; 56.22,49.95 C92.2 ; C92.2 56.68,50.35 ; C92.2 55.76,50.35 ; C92.2 56.31,50.27 v2(56.82,50.27) ; 54.17,34.15 C70.2 54.73,33.59 ; 70.66,32.7 R15.2 ; R15.2 71.27,32.65 C47.2 72.24,33.06 ; R15.2 71.22,33.26 ; v2(48.82,55.87) 48.9,55.95 C96.2 ; 29.19,38.67 C126.1 30.3,38.67 ; v2(73.62,46.29) 73.59,46.33 C48.2 ; 34.89,32.27 C31.2 35.45,32.83 ; C165.2 81.62,26.92 ; C165.2 81.62,25.8 ; C165.2 82.18,26.36 ; 61.65,35.45 C52.2 61.25,34.99 ; 35.25,26.95 C128.2 ; 57.74,24.09 C115.2 58.3,24.65 ; 56.76,55.88 C63.1 56.35,56.34 ; R42.2 46.21,57.24 46.45,57.48 v1(46.84,57.48) ; v2(60.02,49.47) 60.63,49.47 C87.2 ; 53.27,41.25 R40.2 ; R40.2 54.39,41.25 ; 77.37,31.05 C140.2 v1(76.81,31.73) ; 45.63,29.79 C108.2 ; C108.2 v2(45.63,30.94) ; C108.2 45.07,30.35 ; v2(61.62,48.67) 61.7,48.75 C97.2 62.23,48.35 ; 95.86,49.13 R65.1 96.42,48.57 ; 75.79,27.09 C154.2 ; C72.2 52.72,32.61 ; 48.67,33.03 C120.2 49.13,32.63 ; 97.46,36.55 Q2.2 ; Q2.2 98.98,36.55 ; Q2.2 98.22,37.5 ; Q2.2 98.22,35.6 ; C91.2 56.28,49.39 ; C91.2 55.82,49.8 ; C91.2 55.3,49.39 v2(55.22,49.47) ; R119.2 68.82,48.77 ; 21.18,26.02 C129.1 21.64,26.43 ; v2(33.14,28.88) 33.23,28.96 C40.2 33.23,29.6 v2(33.14,29.68) ; 25.55,34.81 C41.2 26.01,35.21 v2(25.95,35.28) 25.73,35.28 25.62,35.38 C24.2 25.22,35.88 ; C75.2 57.58,32.85 ; C75.2 57.02,32.29 ; C75.2 57.02,33.41 ; 51.53,27.49 C110.2 ; 94.84,49.13 C7.1 94.28,48.57 ; v2(48.82,48.67) 49.52,48.67 C86.2 49.92,48.67 v2(50.42,48.67) ; v1(53.72,44.87) R165.2 ; v2(52.02,48.67) 52.5,49.15 C102.2 ; R67.2 101.61,34.74 ; R67.2 v1(101.05,34) ; R67.2 101.05,35.3 ; 101.03,19.56 Q1.2 ; Q1.2 v1(101.98,20.52) ; Q1.2 101.98,18.79 ; Q1.2 102.93,19.56 ; C39.2 28.16,36.08 v2(28.35,36.08) ; C139.1 95.4,52.41 ; C139.1 94.28,52.41 ; C139.1 94.84,51.85 ; 47.43,29.34 47.43,29.34 C112.2 47.52,28.66 v2(47.52,28.14) 47.52,27.64 C114.2 ; 37.7,26.37 C127.2 37.14,25.81 ; 55.59,24.65 C105.2 55.03,24.09 ; R116.2 74.19,50.1 ; C87.2 60.17,49.56 ; C87.2 60.73,50.12 ; v1(88.11,25.09) R2.1 ; R2.1 88.67,24.32 ; R2.1 87.55,24.32 ; C55.2 55.73,41.51 ; C55.2 55.17,40.95 ; C55.2 56.29,40.95 ; 55.32,53.91 C89.2 55.22,54.57 v2(55.22,55.07) ; 60.42,30.99 C69.2 60.98,31.55 ; 95.81,50.12 R54.2 96.37,49.57 ; C142.1 99.58,49.98 ; 69.57,37.36 C174.2 70.13,37.92 ; 45.07,33.15 C90.2 ; C90.2 v2(45.63,32.56) C78.2 ; C90.2 45.63,33.71 ; 77.84,27.07 R77.2 77.84,28.19 ; C114.2 47.43,28.11 ; C114.2 47.43,26.99 ; 50.63,27.42 C118.2 50.17,27.83 ; 61.65,34.45 C53.2 61.25,34.91 ; 45.07,31.95 C78.2 ; C78.2 45.63,31.39 ; 40.23,55.92 C80.2 39.77,55.51 ; C48.2 73.11,46.73 ; C48.2 72.65,46.33 ; C34.2 28.44,38.14 ; 67.92,5.38 P1.9 ; C101.2 43.42,58.16 ; C101.2 43.42,57.05 ; C101.2 42.86,57.6 ; C117.2 56.96,24.83 v2(57.14,24.65) ; C117.2 56.53,24.42 ; C117.2 56.08,24.83 ; v2(33.14,30.48) 33.23,30.56 C27.2 33.23,31.2 v2(33.14,31.28) ; 59.44,34.6 C178.2 58.88,35.16 ; C66.2 53.73,32.9 ; 47.52,35.13 C61.2 ; 95.64,52.4 R63.2 96.05,52.86 ; 34.51,34.38 C37.2 33.95,33.82 ; 25.38,37.87 C29.2 25.94,38.43 ; 98.03,47.39 C147.1 ; R121.2 72.16,43.52 ; 47.1,34.8 C51.2 46.54,34.24 ; 23.92,32.85 C36.2 ; C36.2 25.04,32.85 ; C36.2 24.48,32.29 ; 76.81,27.09 C168.2 ; C88.2 60.82,56.49 v2(60.82,55.87) ; 58.57,24.65 C113.2 ; C113.2 v2(59.83,24.65) C107.2 ; C113.2 59.13,24.09 ; C26.2 31.77,26.68 ; v2(30.74,35.28) C125.1 ; 54.63,31.39 C74.2 ; 58.8,56.48 C94.2 59.21,55.88 v2(59.22,55.87) ; 54.02,35.59 C73.2 ; v2(58.33,27.24) 58.83,27.74 C111.2 ; 66.65,5.38 P1.7 ; C28.2 30.85,38.14 ; v2(57.13,32.15) 57.71,31.57 C162.2 ; 56.07,27.73 C161.2 56.53,27.32 ; 51.33,24.09 C106.2 ; 52.53,24.09 C67.2 ; 53.63,24.09 C109.2
  BOTTOM w0.406: v2(52.33,31.35) 52.63,31.65 52.63,31.95 C72.2 ; v2(34.74,27.28) 34.82,27.35 C128.2 ; v2(53.93,34.55) 54.23,34.25 54.63,34.25 C70.2 ; C115.2 v2(57.14,24.65) ; C59.2 52.43,39.45 v2(51.93,39.45) ; C50.2 63.03,30.95 v2(63.03,30.95) C159.2 v2(63.03,29.74) C160.2 ; C127.2 v1(37.14,27.17) ; C105.2 v2(54.34,24.65) C109.2 ; C28.2 30.74,37.47 v2(30.74,36.88) ; C67.2 v2(51.93,24.65) C106.2
  BOTTOM w0.508: C34.2 28.35,37.49 v2(28.35,36.88) ; C147.1 97.51,47.95 v1(97.25,48.21) ; v1(98.77,50.76) 99.02,50.51 C142.1 ; v1(29.74,39.48) C126.1 ; v1(71.6,42.75) R121.2 ; C35.2 v1(36.45,29.87) ; v1(68.04,48.21) R119.2 ; v1(73.63,50.87) R116.2 ; C29.2 v1(26.64,37.87) ; v1(68.04,47.19) R120.2
  BOTTOM w0.635: 71.03,39.95 E6.1 ; E6.1 71.86,40.84 ; E6.1 71.03,41.73 ; C174.2 v1(69.57,38.92)
  BOTTOM w0.762: 68.04,30.06 68.04,31.32 ; 68.04,31.32 69.1,31.32 ; 68.04,31.32 68.04,32.57 ; 48.49,22.09 C65.2 ; C65.2 49.54,23 ; C65.2 47.43,23 ; 68.04,29.14 68.04,27.89 69.1,27.89 ; 40.81,31.42 C77.2 ; C77.2 41.71,32.47 ; C77.2 41.71,30.37 ; R55.2 102.91,30.24 ; R55.2 102,29.28 ; R55.2 102.91,28.33 ; 102.78,46.11 R58.2 ; R58.2 102.78,48.02 ; R58.2 101.88,47.06 ; 63.6,34.16 C85.2 ; C85.2 62.55,35.06 ; C85.2 64.65,35.06 ; 41.22,34.49 C76.2 ; C76.2 40.17,35.75 ; C76.2 41.22,37.01 ; C104.2 46.62,23 ; C104.2 44.51,23 ; C104.2 45.57,22.09 ; 63.49,25.49 C103.2 62.43,24.59 ; C130.2 20.48,24.9 ; C130.2 19.09,24.9 ; C130.2 19.78,24.27
  vias: v1(1.6,24.71) v1(1.57,21.18) v1(2.42,48.15) v1(2.59,44.62) v1(2.59,21.18) v1(2.87,24.71) v1(3.15,58.24) v1(3.15,53.16) v1(3.15,39.19) v1(3.15,34.11) v1(3.15,16.33) v1(3.15,11.25) v1(3.15,6.17) v1(3.69,48.15) v1(3.86,44.62) v1(3.86,21.18) v1(4.14,24.71) v1(4.96,48.15) v1(5.13,44.62) v1(5.13,21.18) v1(5.41,24.71) v1(5.69,55.7) v1(5.69,36.65) v1(5.69,31.57) v1(5.69,13.79) v1(5.69,8.71) v1(6.23,48.15) v1(6.4,44.62) v1(6.4,21.18) v1(6.68,24.71) v1(7.5,48.15) v1(7.44,21.18) v1(7.67,44.62) v1(7.92,24.96) v1(8.23,58.24) v1(8.23,53.16) v1(8.23,39.19) v1(8.23,34.11) v1(8.23,16.33) v1(8.23,11.25) v1(8.23,6.17) v1(8.64,28.55) v1(8.64,27.28) v1(8.64,26.01) v1(8.7,21.38) v1(8.77,48.15) v1(8.83,29.81) v1(8.94,44.61) v1(9.34,30.97) v1(9.83,21.95) v1(10.03,47.99) v1(10.11,44.12) v1(10.13,31.96) v1(10.77,55.7) v1(10.77,50.62) v1(10.77,41.73) v1(10.77,36.65) v1(10.77,22.81) v1(10.77,18.87) v1(10.77,13.79) v1(10.77,8.71) v1(11.22,47.55) v1(11.21,43.48) v1(11.16,32.71) v1(11.57,23.8) v1(12.05,24.98) v1(12.21,28.78) v1(12.17,27.51) v1(12.17,26.24) v1(12.32,46.92) v1(12.31,42.85) v1(12.34,33.17) v1(13.31,39.19) v1(13.31,21.41) v1(13.31,16.33) v1(13.31,11.25) v1(13.31,6.17) v1(13.42,46.28) v1(13.41,42.21) v1(13.61,33.3) v1(14.07,14.3) v1(14.2,28.01) v1(14.52,45.65) v1(14.51,41.58) v1(14.88,33.3) v1(15.09,15.31) v1(15.47,28.01) v1(15.62,45.01) v1(15.61,40.94) v1(15.85,50.62) v1(15.85,23.95) v1(15.85,18.87) v1(15.85,3.63) v1(16.1,17.35) v1(16.15,33.3) v1(16.72,44.38) v1(16.74,28.01) v1(16.86,38.3) v1(17.12,18.36) v1(17.42,33.3) v1(17.63,27.51) v1(17.82,43.74) v1(18.01,37.67) v1(18.01,17.47) v1(18.39,48.08) v1(18.39,21.41) v1(18.69,33.3) v1(18.64,24.71) v1(18.92,43.11) v1(18.9,27.51) v1(19.02,17.47) v1(19.15,36.78) v1(19.78,35.89) v1(19.78,23.7) v1(19.91,27.51) v1(20.02,42.47) v1(19.96,33.3) v1(20.04,17.47) v1(20.67,35.38) v1(20.93,60.78) v1(20.93,50.62) v1(20.93,45.54) v1(20.93,24.71) v1(20.93,18.87) v1(20.93,3.63) v1(21.18,41.73) v1(21.18,25.73) v1(21.82,35.25) v1(22.45,40.97) v1(23.47,48.08) v1(23.47,40.08) v1(23.47,16.33) v1(23.47,6.17) v1(23.59,24.33) v1(23.72,35.38) v1(24.48,38.68) v1(24.86,37.67) v1(26.01,60.78) v1(26.01,50.62) v1(26.01,3.63) v1(26.39,13.28) v1(27.28,48.08) v1(29.65,24.17) v1(30.07,25.8) v1(30.2,16.84) v1(30.2,15.95) v1(30.2,15.06) v1(30.2,12.65) v1(30.2,11.5) v1(30.2,10.74) v1(30.2,9.98) v1(31.09,60.78) v1(31.09,55.7) v1(31.09,50.62) v1(31.09,15.06) v1(31.09,7.44) v1(31.09,2.36) v1(31.89,25.04) v1(33.63,63.32) v1(33.63,58.24) v1(33.63,4.9) v1(33.88,47.06) v1(35.66,14.3) v1(36.17,60.78) v1(36.17,43.25) v1(36.17,40.97) v1(36.17,7.44) v1(36.17,2.36) v1(36.68,15.31) v1(36.93,45.92) v1(37.06,49.22) v1(37.06,48.21) v1(37.56,47.32) v1(37.56,44.52) v1(37.82,57.1) v1(37.82,54.56) v1(37.82,17.47) v1(38.45,49.98) v1(38.45,47.32) v1(38.45,44.52) v1(38.71,63.32) v1(38.71,57.1) v1(38.71,54.56) v1(38.71,41.98) v1(38.71,4.9) v1(39.34,56.33) v1(39.34,55.32) v1(39.6,17.47) v1(40.49,17.47) v1(40.87,37.28) v1(41.12,34.24) v1(41.25,60.78) v1(41.25,2.36) v1(41.5,17.47) v1(41.76,43) v1(41.76,41.09) v1(42.39,39.57) v1(42.64,49.86) v1(43.15,56.84) v1(43.15,56.08) v1(43.41,51.25) v1(43.79,63.32) v1(43.79,4.9) v1(43.91,38.81) v1(45.06,15.06) v1(45.06,9.98) v1(45.83,36.01) v1(46.33,60.78) v1(46.33,2.36) v1(47.6,12.52) v1(47.6,7.44) v1(50.14,15.06) v1(52.68,12.52) v1(55.22,9.98) v1(56.11,20.27) v1(56.25,15.43) v1(57.12,20.27) v1(57.12,19.25) v1(57.76,65.86) v1(57.76,60.78) v1(57.76,7.44) v1(57.76,2.36) v1(60.3,63.32) v1(60.25,20.2) v1(60.25,19.19) v1(60.3,9.98) v1(60.3,4.9) v1(62.03,24.44) v1(62.84,65.86) v1(62.84,60.78) v1(62.83,24.44) v1(62.84,2.36) v1(63.42,20.2) v1(63.42,19.19) v1(64.11,57.99) v1(64.11,56.97) v1(65.12,58.62) v1(65.38,63.32) v1(66.14,58.62) v1(66.65,48.08) v1(67.41,32.84) v1(67.41,29.54) v1(67.92,65.86) v1(67.92,60.78) v1(67.92,50.62) v1(67.92,2.36) v1(68.43,32.84) v1(68.43,29.54) v1(68.55,37.03) v1(69.2,29.54) v1(69.44,32.84) v1(70.46,63.32) v1(70.46,58.24) v1(70.46,53.16) v1(70.58,39.57) v1(71.6,39.57) v1(71.6,38.43) v1(72.14,33.53) v1(73,65.86) v1(73,60.78) v1(73,55.7) v1(73,7.44) v1(73,2.36) v1(74.78,18.62) v1(75.54,49.35) v1(75.54,46.81) v1(75.79,19.89) v1(76.81,44.27) v1(76.81,40.46) v1(76.81,36.65) v1(77.32,19.89) v1(78.08,34.11) v1(79.09,54.3) v1(79.35,37.92) v1(79.35,20.01) v1(79.98,53.54) v1(79.98,52.65) v1(80.11,23.7) v1(80.24,54.3) v1(80.36,38.43) v1(80.36,37.41) v1(80.36,36.4) v1(80.36,35.51) v1(80.36,34.62) v1(80.36,20.01) v1(80.62,63.32) v1(80.62,3.63) v1(81.38,38.43) v1(81.38,34.36) v1(81.38,20.01) v1(81.51,52.65) v1(81.63,23.7) v1(82.4,38.43) v1(82.4,34.36) v1(82.4,20.01) v1(82.78,54.3) v1(82.78,53.41) v1(82.78,52.65) v1(82.9,50.49) v1(82.9,48.71) v1(82.9,46.17) v1(83.02,32.06) v1(83.16,65.86) v1(83.16,60.78) v1(83.16,23.7) v1(83.16,6.17) v1(83.41,20.01) v1(83.92,51.51) v1(83.92,50.49) v1(83.92,49.6) v1(83.92,48.71) v1(83.92,46.17) v1(84.05,52.65) v1(84.43,47.44) v1(84.43,44.9) v1(84.43,20.01) v1(84.68,24.46) v1(84.94,28.27) v1(84.94,19.12) v1(84.94,18.23) v1(85.7,63.32) v1(85.7,3.63) v1(86.71,28.27) v1(86.71,26.24) v1(86.79,21.94) v1(86.79,21.23) v1(86.79,20.52) v1(86.79,19.81) v1(86.79,19.1) v1(88.24,65.86) v1(88.24,60.78) v1(88.49,50.75) v1(88.49,50.11) v1(88.49,28.27) v1(89.51,50.75) v1(89.51,50.11) v1(89.51,25.98) v1(90.27,25.22) v1(90.52,50.75) v1(90.52,50.11) v1(90.78,63.32) v1(90.78,8.71) v1(90.78,3.63) v1(91.03,28.27) v1(91.03,26.24) v1(91.16,13.54) v1(91.16,12.52) v1(91.16,11.5) v1(92.17,11.5) v1(92.81,28.27) v1(92.81,26.24) v1(93.19,11.5) v1(93.32,65.86) v1(94.21,59.38) v1(94.21,56.84) v1(94.21,13.54) v1(94.21,12.52) v1(94.21,11.5) v1(94.33,44.27) v1(94.33,41.6) v1(94.59,23.95) v1(94.84,28.27) v1(94.84,26.24) v1(95.22,59.38) v1(95.22,56.84) v1(95.35,44.27) v1(95.35,41.6) v1(95.35,21.41) v1(95.6,20.52) v1(95.6,19.63) v1(95.86,63.32) v1(95.86,58.62) v1(95.86,57.6) v1(95.86,56.08) v1(95.86,55.06) v1(95.86,8.71) v1(95.86,3.63) v1(95.98,46.17) v1(95.98,45.16) v1(95.98,43.38) v1(95.98,42.36) v1(96.11,21.41) v1(96.49,20.52) v1(96.62,28.27) v1(96.62,26.24) v1(97.13,25.22) v1(97.64,29.54) v1(97.89,37.79) v1(97.89,35.25) v1(98.4,60.78) v1(98.4,45.54) v1(98.4,41.73) v1(98.4,32.59) v1(98.4,31.06) v1(98.4,27) v1(98.4,11.25) v1(98.4,6.17) v1(99.67,28.27) v1(99.67,23.95) v1(100.68,32.59) v1(100.68,31.06) v1(100.68,29.54) v1(100.94,63.32) v1(100.94,58.24) v1(100.94,43) v1(101.7,48.33) v1(101.7,47.06) v1(101.7,45.79) v1(101.7,30.55) v1(101.7,29.28) v1(101.7,28.01) v1(101.98,12.14) v1(102.21,26.49) v1(102.21,22.68) v1(102.21,15.06) v1(102.72,48.33) v1(102.72,45.79) v1(102.72,30.55) v1(102.72,28.01) v1(103.48,60.78) v1(103.48,6.17) v1(104.48,58.26) v1(104.75,43) v1(106.02,63.32) v1(106.02,16.33) v1(107.29,41.73) v1(107.29,26.49) v1(107.29,22.68) v2(2.08,51.84) v2(2.08,50.82) v2(2.08,49.81) v2(2.08,43.08) v2(2.08,42.06) v2(2.08,41.04) v2(2.08,28.34) v2(2.08,27.33) v2(2.08,26.31) v2(2.08,19.58) v2(2.08,18.57) v2(2.08,17.55) v2(3.1,51.84) v2(3.1,50.82) v2(3.1,49.81) v2(3.1,43.08) v2(3.1,42.06) v2(3.1,41.04) v2(3.1,28.34) v2(3.1,27.33) v2(3.1,26.31) v2(3.1,19.58) v2(3.1,18.57) v2(3.1,17.55) v2(4.11,51.84) v2(4.11,50.82) v2(4.11,49.81) v2(4.11,43.08) v2(4.11,42.06) v2(4.11,41.04) v2(4.11,28.34) v2(4.11,27.33) v2(4.11,26.31) v2(4.11,19.58) v2(4.11,18.57) v2(4.11,17.55) v2(5.13,51.84) v2(5.13,50.82) v2(5.13,49.81) v2(5.13,43.08) v2(5.13,42.06) v2(5.13,41.04) v2(5.13,28.34) v2(5.13,27.33) v2(5.13,26.31) v2(5.13,19.58) v2(5.13,18.57) v2(5.13,17.55) v2(6.15,51.84) v2(6.15,50.82) v2(6.15,49.81) v2(6.15,43.08) v2(6.15,42.06) v2(6.15,41.04) v2(6.15,28.34) v2(6.15,27.33) v2(6.15,26.31) v2(6.15,19.58) v2(6.15,18.57) v2(6.15,17.55) v2(18.85,12.7) v2(18.85,11.88) v2(18.85,11.07) v2(19.66,12.7) v2(19.66,11.07) v2(20.47,12.7) v2(20.47,11.88) v2(20.47,11.07) v2(40.44,12.7) v2(40.44,11.88) v2(40.44,11.07) v2(41.25,12.7) v2(41.25,11.07) v2(41.76,32.59) v2(41.76,30.17) v2(42.06,12.7) v2(42.06,11.88) v2(42.06,11.07) v2(44.3,23.19) v2(46.72,35.05) v2(46.96,23.19) v2(49.76,23.19) v2(56.43,40.85) v2(57.13,27.15) v2(60.02,51.87) v2(60.82,51.87) v2(60.93,44.45) v2(61.25,34.95) v2(61.62,43.06) v2(61.62,42.26) v2(75.33,26.95) v2(75.33,25.73) v2(75.33,24.51) v2(75.94,26.34) v2(75.94,25.12) v2(76.55,26.95) v2(76.55,25.73) v2(76.55,24.51) v2(77.16,26.34) v2(77.16,25.12) v2(77.77,26.95) v2(77.77,25.73) v2(77.77,24.51) v2(88.76,20.57) v2(89.78,21.59) v2(89.78,19.56) v2(90.8,21.59) v2(90.8,20.57) v2(90.8,19.56) v2(92.73,51.71) v2(92.73,50.49) v2(92.73,49.27) v2(93.34,51.1) v2(93.34,49.88) v2(93.95,51.71) v2(93.95,50.49) v2(93.95,49.27) v2(94.56,51.1) v2(94.56,49.88) v2(95.17,51.71) v2(95.17,50.49) v2(95.17,49.27)
VCCPINT: length 21.6
  TOP w0.305: U4.G6 v2(55.53,35.35) ; U4.K5 v2(52.33,36.15) ; U4.G10 v2(55.53,31.35) ; U4.J10 v2(53.13,31.35) ; U4.E10 v2(57.13,31.35) ; U4.L10 v2(51.53,31.35) ; U4.F9 v2(56.33,32.15) ; U4.H5 v2(54.73,36.15)
  TOP w0.508: 56.43,22.69 C68.1 56.99,22.13
  TOP w0.762: E1.2 71.92,16.84 ; E1.2 71.92,15.06 ; E1.2 71.09,15.95 ; C64.1 63.16,22.49 ; C64.1 61.9,23.54 ; C64.1 60.64,22.49 ; C71.1 59.9,22.55 ; C71.1 58.65,23.61 ; C71.1 57.39,22.55
  BOTTOM w0.406: v2(54.73,36.15) 54.73,36.15 C70.1 55.33,35.14 v2(55.53,35.35) ; v2(55.53,31.35) 55.53,31.85 C74.1 55.73,32.05 56.23,32.05 v2(56.33,32.15) 56.33,32.55 C75.1 ; C72.1 51.53,31.84 v2(51.53,31.35) ; v2(53.13,31.35) 53.72,31.35 C66.1 ; C73.1 52.33,36.15 v2(52.33,36.15)
  vias: v1(57.2,22.87) v1(57.2,22.11) v1(60.25,22.87) v1(60.25,22.11) v1(63.42,22.87) v1(63.42,22.11) v1(69.95,17.85) v1(69.95,17.09) v1(69.95,16.33) v1(69.95,15.57) v1(69.95,14.81) v1(70.71,17.85) v1(70.71,17.09) v1(70.71,16.33) v1(70.71,15.57) v1(70.71,14.81) v1(71.47,17.85) v1(71.47,17.09) v1(72.24,17.85) v1(72.24,17.09)
VCCPLL: length 12.7
  TOP w0.305: U4.F5 v2(56.33,36.15)
  BOTTOM w0.152: 57.94,36.15 57.53,36.55 56.73,36.55 56.33,36.15 v2(56.33,36.15) 56.34,36.15 56.73,35.75 57.54,35.75 57.94,36.15
  BOTTOM w0.508: 57.94,36.15 C178.1 59.64,36.35 61.14,36.35 61.76,36.97 C85.1
  BOTTOM w0.635: C85.1 64.17,36.97 64.62,37.41 L12.2
VDD33_USB: length 4.7
  TOP w0.305: U15.20 79.6,25.48 79.73,25.35 v1(80.36,25.35) ; U15.23 79.58,26.98 v1(79.86,27.25)
  BOTTOM w0.508: v1(80.36,25.35) 80.63,25.61 C165.1 80.63,26.48 v1(79.86,27.25)
VDD_INTERFACE: length 21.1
  TOP w0.305: C33.1 32.29,16.08 C32.1 ; C33.1 32.7,17.09 ; C33.1 32.29,17.55 ; U5.H12 28.81,27.61 28.81,27.16 v2(28.83,27.14) C43.1 28.83,25.15 C45.1 ; R5.1 v1(24.99,10.61)
  TOP w0.635: E4.2 33.25,14.93 ; E4.2 32.36,14.11 ; E4.2 34.14,14.11 ; 33.06,15.95 C32.1 32.42,15.25
  BOTTOM w0.305: v1(33.37,15.31) 31.85,13.79 28.17,13.79 v1(24.99,10.61) ; C44.1 28.83,27.26 28.83,27.26 v2(28.83,27.14) 28.83,26.75 C38.1
  vias: v1(32.99,16.84) v1(33.37,15.95) v1(33.63,16.84) v1(34.01,15.95) v1(34.01,15.31) v1(34.26,16.84)
VDDA1P1_RX_VCO: length 3.1
  TOP w0.305: U5.G2 v2(29.14,36.08) ; U5.G3 v2(29.14,35.28)
  BOTTOM w0.305: v2(29.14,36.08) 29.73,36.08 R51.2 29.63,35.94 C125.2 v2(29.15,35.28)
VIN: length 45.6
  TOP w0.203: 36.31,52.23 U14.10 36.95,51.88
  TOP w0.305: U6.14 93.2,53.78 v1(92.94,54.05) ; v1(98.91,54.68) 98.72,54.49 R56.1 ; C8.1 97.45,21.74 ; C8.1 97.45,20.82 ; C8.1 97.85,21.28 ; v1(67.03,13.15) R81.1 ; 92.2,47.34 U6.25 92.11,47.95 91.92,47.95 91.67,47.7 ; 36.74,50.54 C62.2 ; C62.2 36.74,51.46 ; C62.2 36.33,51 ; v1(92.94,46.94) 93.2,47.2 U6.27 ; 92.2,53.64 U6.16 92.08,53.07 91.89,53.07 91.69,53.27 ; U15.21 v1(79.86,25.98) 80.8,25.98 C164.1 80.94,26.68 81.13,26.87 81.51,26.87 81.63,27 81.63,27.52 R75.1 ; U11.8 65.27,14.26 C167.1 65.44,14.87 v1(65.26,15.05) ; v1(67.03,11.63) R80.1 ; U6.15 92.7,53.64 ; 92.7,47.34 U6.26
  TOP w0.508: DS1.A v1(106.78,19.29) ; DS2.A v1(106.91,10.91)
  TOP w0.635: C9.1 98.59,19.38 ; C9.1 97.95,20.08 ; C9.1 97.95,18.68
  TOP w0.762: 85.06,33.41 E7.2 ; E7.2 86.84,33.41 ; E7.2 85.95,34.24 ; C157.1 85.61,36.4 ; C157.1 84.55,37.65 ; C157.1 84.55,35.14 ; L1.1 97.77,17.97 ; L1.1 97.77,15.45 ; L1.1 98.64,16.71 ; 92.85,57.26 C138.1 ; C138.1 92.85,58.96 ; C138.1 92.05,58.11 ; 92.97,42.15 C137.1 ; C137.1 92.97,43.85 ; C137.1 92.17,43 ; 92.05,55.57 C136.1 ; C136.1 92.85,54.72 ; C136.1 92.85,56.42 ; 92.97,44.69 C135.1 ; C135.1 92.97,46.39 ; C135.1 92.17,45.54
  BOTTOM w0.305: v1(92.94,46.94) 92.94,46.44 R59.2 ; v1(35.79,51) R221.1 R222.1
  vias: v1(35.79,50.24) v1(36.42,50.24) v1(85.95,38.17) v1(85.95,37.54) v1(85.95,36.9) v1(85.95,36.27) v1(85.95,35.63) v1(86.59,38.17) v1(86.59,37.54) v1(86.59,36.9) v1(86.59,36.27) v1(86.59,35.63) v1(91.54,59.38) v1(91.54,58.75) v1(91.54,58.11) v1(91.54,57.48) v1(91.54,56.21) v1(91.54,55.57) v1(91.54,54.94) v1(91.67,46.05) v1(91.67,45.41) v1(91.67,44.78) v1(91.67,43.51) v1(91.67,42.87) v1(91.67,42.24) v1(91.67,41.6) v1(92.17,59.38) v1(92.3,41.6) v1(92.81,59.38) v1(92.94,41.6) v1(98.14,21.41) v1(98.14,20.77) v1(98.78,21.41) v1(98.78,20.77) v1(98.78,20.14) v1(98.78,19.5) v1(98.78,18.87) v1(99.41,21.41) v1(99.41,20.77) v1(99.41,20.14) v1(99.41,19.5) v1(99.41,18.87)
VIN_5V_USB: length 8.3
  TOP w0.254: U9.A1 102.58,38.17 ; U9.A1 U9.B1 102.08,38.17 ; U9.A1 102.96,37.79 ; U8.A1 U8.B1 101.52,53.19
  TOP w0.305: 94.63,36.16 U10.1 93.71,35.75 ; R71.1 96.16,36.03 ; R71.1 95.04,36.03 ; R71.1 95.6,35.47
  TOP w0.762: R73.1 95.93,32.71 ; R73.1 95.03,31.76 ; R73.1 95.03,33.67
  vias: v1(94.84,33.98) v1(94.84,31.44) v1(95.6,33.98) v1(95.6,31.44) v1(96.37,33.73) v1(96.37,32.97) v1(96.37,32.2) v1(96.37,31.44) v1(100.56,54.43) v1(100.56,53.79) v1(100.56,53.16) v1(101.19,54.43) v1(101.19,53.79) v1(101.19,53.16) v1(102.21,39.19) v1(102.21,38.55) v1(102.84,39.19) v1(102.84,38.55) v1(103.48,39.19) v1(103.48,38.55)
VIN_5V_USB_DATA: length 5.2
  TOP w0.254: 102.2,36.66 102.08,36.78 ; 102.08,36.78 U9.B2 U9.A2 ; 102.08,36.78 100.54,36.78 R70.1 ; U9.A2 102.96,37.29 ; U9.A2 102.58,36.91
  TOP w0.406: P2.1 103.48,35.97
VIN_5V_USB_POWER: length 26.5
  TOP w0.203: R68.1 102.96,52.13 103.22,52.4 103.22,53.16
  TOP w0.254: U8.A2 U8.B2 102.78,53.19 ; U8.A2 102.4,54.07 ; U8.A2 102.78,53.69
  TOP w0.305: R68.1 102.96,50.51 v1(103.21,50.25)
  TOP w0.406: P3.1 103.86,53.75
  L5_SIG w0.305: v1(98.14,33.73) 98.14,34.49 99.16,35.51 99.16,45.29 100.56,46.68 100.56,49.35 101.46,50.25 v1(103.21,50.25)
  BOTTOM w0.305: v1(98.14,33.73) 99.02,33.73 R66.1
1P3_SUPPLY_A: length 68.7
  TOP w0.203: 41.57,14.56 41.69,14.68 42.06,14.68 42.22,14.51 U7.9
  TOP w0.305: 40.23,15.73 C16.1 ; C16.1 40.69,16.14 ; C16.1 39.77,16.14 ; 41.5,15.73 C18.1 ; C18.1 41.04,16.14 ; C18.1 41.96,16.14 ; U5.F2 v2(30.74,36.08) ; 38.57,12.86 U7.13 ; U7.13 39.35,13.29 ; U7.13 U7.14 ; U7.12 40.27,14.56 ; U7.12 39.84,13.78 ; U7.12 U7.11 U7.10 41.57,14.56 ; U5.B10 v2(33.94,28.88) ; U5.J3 v2(27.55,35.28) ; U5.K3 v2(26.74,35.28) ; U5.E2 v2(31.54,36.08) ; U5.B9 v2(33.94,29.68)
  TOP w0.635: 38.01,16.01 C14.1 ; C14.1 39.41,16.01 ; C14.1 38.71,15.38 ; C15.1 38.52,14.3 ; C15.1 37.88,15 ; C15.1 37.88,13.6
  BOTTOM w0.305: 31.46,36.08 v2(30.74,36.08) ; 31.46,36.08 31.33,36.2 C23.1 31.33,36.96 31.84,37.47 C28.1 ; 31.46,36.08 v2(31.54,36.08) ; C29.1 26.26,36.57 C24.1 26.49,35.64 26.49,35.53 v2(26.74,35.28) ; v2(33.94,28.88) 33.86,28.96 C40.1 33.86,29.6 v2(33.94,29.68) ; v2(27.55,35.28) 27.33,35.5 C39.1 27.33,36.46 27.45,36.58
  BOTTOM w0.406: v2(33.94,28.88) 33.95,28.88 C35.1
  BOTTOM w0.508: C29.1 24.5,36.88 23.47,37.92 23.47,38.94 24.36,39.82 24.36,44.67 v1(24.74,45.05) v1(24.74,45.85) ; v1(28.67,46.94) v1(28.67,46.17) 27.45,44.95 C34.1 27.45,36.58 ; v1(31.84,46.87) v1(31.84,46.07) C28.1
  BOTTOM w0.635: v1(37.85,20.27) v1(38.71,20.27) 38.71,20.28 38.71,27.76 37.59,28.88 C35.1
  vias: v1(37.82,16.08) v1(37.82,15.19) v1(38.71,15.19) v1(38.83,14.3) v1(39.6,16.08) v1(39.6,15.19) v1(40.87,16.08) v1(42.14,16.08)
1P3_SUPPLY_B: length 104.9
  TOP w0.203: U1.9 20.63,14.51 20.47,14.68 20.1,14.68
  TOP w0.305: U5.D3 v2(32.34,35.28) ; U5.A8 v2(33.94,31.28) ; U1.11 U1.10 19.98,14.56 ; U1.11 U1.12 ; U1.11 19.33,14.56 ; 18.64,15.73 C5.1 ; C5.1 18.18,16.14 ; C5.1 19.1,16.14 ; U5.D2 v2(32.34,36.08) ; 19.91,15.73 C6.1 ; C6.1 20.37,16.14 ; C6.1 19.45,16.14 ; U5.A9 v2(34.74,30.48) ; U5.A10 v2(34.74,29.68) ; U1.13 17.76,13.29 ; U1.13 16.98,12.86 ; U1.13 U1.14 16.98,12.21 ; U5.K4 v2(26.74,34.48) ; U1.12 18.68,14.56 ; U1.12 18.25,13.78 ; U5.M9 v2(25.14,29.68) ; U5.E3 v2(31.54,35.28) ; U5.B8 v2(33.94,30.48) ; U5.M10 v2(25.14,28.88) ; U5.A7 v2(34.74,31.28) ; U5.F12 v2(30.74,27.28)
  TOP w0.635: L9.1 v1(21.14,33.09) ; 17.12,15.38 C4.1 ; C4.1 17.82,16.01 ; C4.1 16.42,16.01 ; v1(21.14,27.63) 22.17,27.63 L8.1 ; C3.1 16.93,14.3 ; C3.1 16.29,15 ; C3.1 16.29,13.6
  BOTTOM w0.305: C30.1 30.73,25.95 C26.1 30.73,27.26 v2(30.74,27.28) ; v1(21.14,27.63) 21.18,27.59 C129.2 20.74,27.06 19.98,26.3 C130.1 ; v2(26.74,34.48) 26.45,34.18 26.01,34.18 C41.1 25.68,33.84 C36.1 ; v2(33.94,31.28) 33.86,31.2 C27.1 33.86,30.56 v2(33.94,30.48)
  BOTTOM w0.406: 32.34,35.37 v2(32.34,36.08) ; 32.34,35.37 v2(32.34,35.28) v2(31.54,35.28) ; 32.34,35.37 32.47,35.49 C42.1 33.83,35.49 C37.1 ; v2(34.74,29.68) 34.74,29.68 v2(34.74,30.48) ; v2(34.74,31.28) v2(33.94,31.28) ; v2(34.74,31.28) 34.74,31.28 v2(34.74,30.48) ; v2(34.74,31.28) 34.75,31.28 C31.1 35.45,30.78 35.15,30.48 v2(34.74,30.48) ; v2(34.74,30.48) 34.74,30.48 v2(33.94,30.48)
  BOTTOM w0.508: v1(33.24,43.19) v1(33.24,42.39) 33.24,39.38 35.5,37.13 35.5,35.73 35.14,35.37 C37.1 ; C31.1 36.25,31.28 36.75,31.78 36.75,37.68 34.55,39.88 v1(34.55,42.39) v1(34.55,43.19) ; v2(25.14,29.68) 25.14,29.68 v2(25.14,28.88) 23.9,27.63 v1(21.14,27.63) v1(21.14,33.09) ; v1(14.09,36.18) v1(14.91,36.18) 16.73,34.36 23.96,34.36 C36.1
  BOTTOM w0.635: v1(21.05,20.65) v1(21.82,20.65) 27.91,20.65 30.9,23.63 C30.1 ; v1(14.09,26.5) v1(14.91,26.5) 15.11,26.3 C130.1
  vias: v1(16.23,16.08) v1(16.23,15.19) v1(17.12,15.19) v1(17.24,14.3) v1(18.01,16.08) v1(18.01,15.19) v1(19.28,16.08) v1(20.55,16.08)
